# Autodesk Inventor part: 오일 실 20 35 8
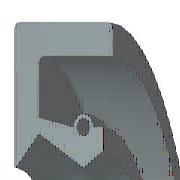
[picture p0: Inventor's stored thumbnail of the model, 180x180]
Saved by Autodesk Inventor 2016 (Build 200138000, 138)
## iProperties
IsCustomPart: 0
Created: 2018-09
Part Number: 오일 실 20 35 8
Material: 고무
Description: 오일-실
Document SubType Name: Modeling
Standard: KS B 2804
Standards Organization: KS
Language: ko-KR
Size Designation: D - 20 35 8
Categories: <MemberInstance><Categories><Category DisplayName="샤프트 부품" InternalName="7f7aeb1f-a693-4053-b835-cee3144e0d98" Mnemonic="SHFT"><Category DisplayName="실링" Intern
Density: 0.93 g/cm^3
Mass: 2.54606 g
Surface Area: 35.9421 cm^2
Volume: 2.7377 cm^3
Appearance: 보라색
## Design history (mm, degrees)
revolve "본체" stored, may be unused: angle "d17" = 90 deg
revolve "스프링1" stored, may be unused: angle "d18" = 90 deg
body "Solid1"
sketch "스케치1"
  geometry: L1 (0, 17.5)-(8, 17.5); L2 (8, 15.75)-(1.75, 15.75); L3 (1.75, 11.75)-(4.9, 10); L4 (4.9, 10)-(0, 10); L5 (0, 0)-(9.586, 0) reference; L6 (4.9, 10)-(6.3, 10.875); L7 (0, 18)-(0, -3) reference; L8 (-1.941, 0)-(11.507, 0) reference; L9 (4.2, 12.1)-(1.75, 12.71); L10 (1.75, 12.71)-(1.75, 15.75); L11 (0, 17.5)-(0, 10.088); L12 (4.9, 10)-(0, 10); L13 (1.75, 11.75)-(0.152, 10.028); L14 (8, 17.5)-(8, 15.75); L15 (5.6, 12.1)-(6.3, 12.1); L16 (6.3, 12.1)-(6.3, 10.875); C1 r 0.455 at (4.9, 12.1); A1 r 0.7 centre (4.9, 12.1) between (5.6, 12.1) and (4.2, 12.1); A2 r 0.088 centre (0.088, 10.088) between (0, 10.088) and (0.152, 10.028); 1 further point
  constraints: 28 end point, 5 horizontal alignment, 5 point on line, 4 point on circle, 4 vertical alignment, 3 centre point, 3 tangent, 2 collinear, 2 horizontal, 2 perpendicular, 1 coincident, 1 parallel
  dimensions: "d0" = 35 diameter of L1 L5 (= SD2); "d1" = 1.75 distance of L1.end L2.start (= SD); "d2" = 0.91 diameter of C1 (= SPDI); "d3" = 1.4 diameter of A1 (= SPDA); "d4" = 20 diameter of L3.end L5 (= NND); "d5" = 23.5 diameter of L3.start L5 (= TKDM); "d7" = 25.42 diameter of L9.end L5 (= TKDM + 0.24 x SWDT); "d8" = 1.75 distance between parallel lines of L11 L10 (= SD); "d9" = 4.9 distance from line of L11 C1.centre (= SPDST); "d10" = 24.2 diameter of C1.centre L5 (= HLDM); "d11" = 0.0875 radius of A2 (= 0.25 x LAB); "d12" = 6.3 distance between parallel lines of L11 L16 (= SDI); "d13" = 21.75 diameter of L6.end L5 (= ABDM); "d14" = 8 distance from line of L11 L1.end (= SWDT)
fillet "모깎기1" dims "d6" = 0.3 (= RR)
other parameters: "SD2" = 35 [user parameter; used in 1 equation term], "SWDT" = 8 [user parameter; used in 2 equation terms], "RR" = 0.3 [user parameter; used in 1 equation term], "SD" = 1.75 [user parameter; used in 2 equation terms], "NND" = 20 [user parameter; used in 1 equation term], "SPDA" = 1.4 [user parameter; used in 1 equation term], "SPDI" = 0.91 [user parameter; used in 1 equation term], "TKDM" = 23.5 [user parameter; used in 2 equation terms], "HLDM" = 24.2 [user parameter; used in 1 equation term], "ABDM" = 21.75 [user parameter; used in 1 equation term], "SDI" = 6.3 [user parameter; used in 1 equation term], "SPDST" = 4.9 [user parameter; used in 1 equation term], "LAB" = 0.35 [user parameter; used in 1 equation term], "d15" = 0, "d16" = 0, "d19" = 0
